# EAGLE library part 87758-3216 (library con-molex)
32 Pin - 2mm Dual Row Single Wafer, Vertical T/H HDR Source: http://www.molex.com/pdm_docs/sd/877580616_sd.pdf
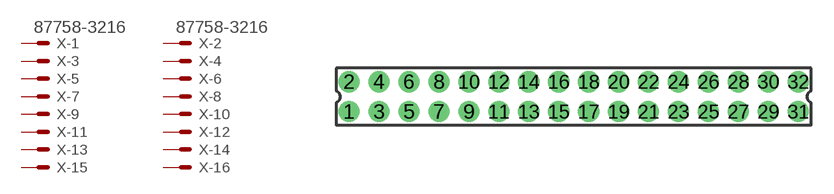
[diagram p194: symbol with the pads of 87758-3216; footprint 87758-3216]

Designator prefix X; gates -1=MV -2=MV -3=M -4=M -5=M -6=M -7=M -8=M -9=M -10=M -11=M -12=M -13=M -14=M -15=M -16=M -17=M -18=M -19=M -20=M -21=M -22=M -23=M -24=M -25=M -26=M -27=M -28=M -29=M -30=M -31=M -32=M

## 87758-3216 (MPN: 87758-3216; OC_FARNELL: unknown; OC_NEWARK: 25M5684)  [87758-3216]
1  -1:S  pas
2  -2:S  pas
3  -3:S  pas
4  -4:S  pas
5  -5:S  pas
6  -6:S  pas
7  -7:S  pas
8  -8:S  pas
9  -9:S  pas
10  -10:S  pas
11  -11:S  pas
12  -12:S  pas
13  -13:S  pas
14  -14:S  pas
15  -15:S  pas
16  -16:S  pas
17  -17:S  pas
18  -18:S  pas
19  -19:S  pas
20  -20:S  pas
21  -21:S  pas
22  -22:S  pas
23  -23:S  pas
24  -24:S  pas
25  -25:S  pas
26  -26:S  pas
27  -27:S  pas
28  -28:S  pas
29  -29:S  pas
30  -30:S  pas
31  -31:S  pas
32  -32:S  pas

## Footprint 87758-3216 (pad centres in mm)
32 Pin - 2mm Dual Row Single Wafer, Vertical T/H HDR Source: http://www.molex.com/pdm_docs/sd/877580616_sd.pdf
drill 0.9 pad 1.27 round: 1 -15,-1; 2 -15,1; 3 -13,-1; 4 -13,1; 5 -11,-1; 6 -11,1; 7 -9,-1; 8 -9,1; 9 -7,-1; 10 -7,1; 11 -5,-1; 12 -5,1; 13 -3,-1; 14 -3,1; 15 -1,-1; 16 -1,1; 17 1,-1; 18 1,1; 19 3,-1; 20 3,1; 21 5,-1; 22 5,1; 23 7,-1; 24 7,1; 25 9,-1; 26 9,1; 27 11,-1; 28 11,1; 29 13,-1; 30 13,1; 31 15,-1; 32 15,1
